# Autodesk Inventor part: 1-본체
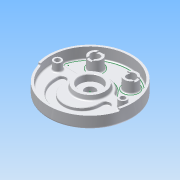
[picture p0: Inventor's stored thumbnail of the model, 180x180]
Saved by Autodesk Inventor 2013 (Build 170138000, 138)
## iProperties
Created: 2015-06
Part Number: 1-본체
Material: 알루미늄 6061
Document SubType Name: Modeling
Designer: Administrator
Mass: 959.322 g
Surface Area: 1038.99 cm^2
Volume: 398.503 cm^3
Density: 2.40731 g/cm^3
Author: Administrator
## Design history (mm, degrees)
sketch "스케치1"
  geometry: C1 r 95 at (0, 0); 1 further point
  constraints: 1 centre point, 1 coincident
  dimensions: "d0" = 190 diameter of C1
extrude "돌출1" new body sketch "스케치1" distance "d2" = 32; taper "d3" = 0 deg
sketch "스케치2"
  geometry: C1 r 95 at (0, 0) reference; C2 r 90 at (0, 0)
  constraints: 1 centre point, 1 coincident
  dimensions: "d4" = 180 diameter of C2
extrude "돌출2" cut sketch "스케치2" distance "d6" = 25; taper "d7" = 0 deg
sketch "스케치3"
  geometry: L1 (-95, 0)-(95, 0); L2 (-86.318, -25.48)-(-91.32, -26.184); L3 (86.769, -23.898)-(91.76, -24.6); A1 r 90 centre (0, 0) between (-86.318, -25.48) and (86.769, -23.898) reference; A2 r 95 centre (0, 0) between (-95, 0) and (95, 0) reference
  constraints: 6 end point, 6 point on circle, 1 horizontal
  dimensions: "d8" = 8 deg angle of L3 L1; "d11" = 5.00273 horizontal distance of L2.start L2.end; "d12" = 4.9907 horizontal distance of L3.start L3.end; "d25" = 8 deg angle of L2 L1
extrude "돌출3" cut sketch "스케치3" distance "d13" = 5; taper "d14" = 0 deg
sketch "스케치4"
  geometry: L1 (-90, 0)-(90, 0); L2 (-90, -19)-(90, -19); L3 (-90, 16)-(-38.833, 16); L4 (38.833, 16)-(90, 16); L5 (-90, -14)-(90, -14); L6 (-59, -19)-(-59, -14); L7 (-41, -19)-(-41, -14); L8 (59, -19)-(59, -14); L9 (41, -19)-(41, -14); A1 r 90 centre (0, 0) between (90, 0) and (-90, 0) reference; A2 r 41 centre (0, -19) between (-41, -19) and (41, -19); A3 r 59 centre (0, -19) between (-59, -19) and (59, -19); A4 r 42 centre (0, 0) between (38.833, 16) and (-38.833, 16); A5 r 9 centre (50, -14) between (59, -14) and (41, -14); A6 r 9 centre (-50, -14) between (-41, -14) and (-59, -14); A7 r 90 centre (0, 0) between (-88.566, 16) and (88.566, 16); 2 further points
  constraints: 18 end point, 14 point on circle, 8 point on line, 7 parallel, 6 centre point, 5 tangent, 4 coincident, 3 midpoint, 1 collinear, 1 horizontal, 1 vertical, 1 vertical alignment
  dimensions: "d18" = 19 distance between parallel lines of L2 L1; "d21" = 42 radius of A4; "d22" = 16 distance between parallel lines of L1 L3; "d23" = 41 radius of A2; "d24" = 59 radius of A3; "d26" = 5 distance between parallel lines of L2 L5; "d30" = 18 diameter of A5; "d31" = 9 radius of A6; "d32" = 180 diameter of A7
extrude "돌출4" join sketch "스케치4" distance "d33" = 7; taper "d34" = 0 deg
sketch "스케치5"
  geometry: C1 r 15 at (-40, 52); C2 r 15 at (40, 52); A1 r 42 centre (0, 0) between (38.833, 16) and (-38.833, 16) reference
  constraints: 2 centre point, 1 equal radius, 1 horizontal alignment
  dimensions: "d35" = 52 vertical distance of A1.centre C2.centre; "d36" = 40 horizontal distance of C2.centre A1.centre; "d37" = 80 distance of C1.centre C2.centre; "d38" = 30 diameter of C1
extrude "돌출5" join sketch "스케치5" stored distance "d39" = 14; taper "d40" = 0 deg
hole "구멍1" diameter "d47" = 20; stored, may be unused: countersink angle "d51" = 90 deg, drill point angle "d53" = 118 deg; dims "d45" = 10, "d46" = 10, "d48" = 6, "d49" = 4, "d50" = 2, "d52" = 8
hole "구멍2" diameter "d56" = 20; stored, may be unused: countersink angle "d60" = 90 deg, drill point angle "d62" = 118 deg; dims "d54" = 10, "d55" = 10, "d57" = 6, "d58" = 4, "d59" = 2, "d61" = 8
sketch "스케치7"
  geometry: L1 (-6, -13.748)-(-6, 13.748); L2 (6, 13.748)-(6, -13.748); L3 (66.252, 6)-(93.748, 6); L4 (66.252, -6)-(93.748, -6); C1 r 10 at (0, 0) reference; C2 r 10 at (80, 0) reference; A1 r 15 centre (0, 0) between (6, -13.748) and (-6, -13.748) reference; A2 r 15 centre (80, 0) between (93.748, 6) and (93.748, -6) reference; 1 further point
  constraints: 8 end point, 8 point on circle, 2 parallel, 1 perpendicular, 1 vertical
  dimensions: "d63" = 6 distance from line of L1 C1.centre; "d64" = 12 distance between parallel lines of L2 L1; "d65" = 6 distance from line of C2.centre L3; "d66" = 12 distance between parallel lines of L4 L3
extrude "돌출6" cut sketch "스케치7" distance "d67" = 3; taper "d68" = 0 deg
sketch "스케치8"
  geometry: C1 r 9 at (-74, 0); C2 r 35 at (0, 0); C3 r 9 at (74, 0); A1 r 42 centre (0, 0) between (38.833, 16) and (-38.833, 16) reference; A2 r 90 centre (0, 0) between (-88.566, 16) and (88.566, 16) reference
  constraints: 3 centre point, 2 horizontal alignment, 1 coincident, 1 equal radius
  dimensions: "d69" = 148 distance of C3.centre C1.centre; "d71" = 74 distance of A1.centre C1.centre; "d72" = 18 diameter of C1; "d73" = 70 diameter of C2
extrude "돌출7" join sketch "스케치8" distance "d74" = 10; taper "d75" = -10 deg
extrude "돌출8" join sketch "스케치8" stored distance "d76" = 10; taper "d77" = 0 deg
hole "구멍3" diameter "d80" = 23; stored, may be unused: countersink angle "d84" = 90 deg, drill point angle "d86" = 118 deg; dims "d78" = 10, "d79" = 10, "d81" = 6, "d82" = 50, "d83" = 15, "d85" = 8
sketch "스케치9"
  geometry: C1 r 95 at (0, 0) reference; C2 r 26 at (0, 0)
  constraints: 1 centre point, 1 coincident
  dimensions: "d87" = 52 diameter of C2
extrude "돌출9" join sketch "스케치9" distance "d89" = 12; taper "d90" = -15 deg
hole "구멍4" diameter "d93" = 23; stored, may be unused: countersink angle "d97" = 90 deg, drill point angle "d99" = 118 deg; dims "d91" = 10, "d92" = 10, "d94" = 6, "d95" = 50, "d96" = 15, "d98" = 8
sketch "스케치10"
  geometry: C1 r 9 at (-74, 0) reference; C2 r 9 at (74, 0) reference; 2 further points
  constraints: 2 coincident
hole "구멍5" sketch "스케치10" at (-74, 0), (74, 0) diameter "d100" = 11; stored, may be unused: countersink angle "d104" = 90 deg, drill point angle "d106" = 118 deg; dims "d101" = 6, "d102" = 18, "d103" = 11, "d105" = 8
fillet "모깎기1" dims "d107" = 10
fillet "모깎기2" dims "d108" = 3
fillet "모깎기3" dims "d109" = 3, "d125" = 1
chamfer "모따기1" distance "d110" = 1; stored, may be unused: second distance "d111" = 2, angle "d112" = 45 deg
fillet "모깎기4" dims "d113" = 3
fillet "모깎기5" dims "d114" = 3, "d123" = 5
sketch "스케치11"
  geometry: C1 r 28.302 at (0, 0) reference; C2 r 68 at (0, 0)
  constraints: 1 centre point, 1 coincident, 1 other
  dimensions: "d115" = 136 diameter of C2
feature "엠보싱1" sketch "스케치11" dims "d3" = 0, "d117" = 0.5, "d118" = 0
chamfer "모따기2" distance "d119" = 1; stored, may be unused: second distance "d120" = 2, angle "d121" = 45 deg
fillet "모깎기6" dims "d122" = 3
fillet "모깎기7" dims "d124" = 0.3
sketch "스케치12"
  geometry: L1 (-45.033, 19)-(-75.657, 19) reference; L2 (75.657, 19)-(45.033, 19) reference; C1 r 18 at (-40, 52) reference; C2 r 18 at (40, 52) reference; A1 r 7 centre (-45.033, 26) between (-45.033, 19) and (-38.971, 22.5) reference; A2 r 45 centre (0, 0) between (38.971, 22.5) and (-38.971, 22.5) reference; A3 r 7 centre (45.033, 26) between (38.971, 22.5) and (45.033, 19) reference; A4 r 7 centre (75.657, 26) between (75.657, 19) and (82.277, 28.275) reference; A5 r 87 centre (0, 0) between (82.277, 28.275) and (-82.277, 28.275) reference; A6 r 7 centre (-75.657, 26) between (-82.277, 28.275) and (-75.657, 19) reference
node "솔리드1"
node "투영된 루프2"
other parameters: "d15" = 84, "d17" = 16, "d19" = 59, "d20" = 41, "d29" = 18
